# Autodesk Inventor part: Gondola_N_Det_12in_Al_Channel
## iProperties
Shininess: 64.0
Length Units: 11272
Angle Units: 11279
Time Units: 11290
Mass Units: 11286
Length Display Precision: 3
Angle Display Precision: 2
Compacted: True
Part Number: Gondola_N_Det_12in_Al_Channel
Document SubType Name: Modeling
Created: 2004-12
Designer: John Blackburn
Material: Aluminum-6061
Description: AL. Assoc. 8" 6061-T6 Channel
Manufacturer: Standard
Standards Organization: Custom
Density: 0.0
Volumn: 0.0
Area: 0.0
PropertySet Name: Model Information
Control State: 0
Master: False
Checked Out: False
Author: John Blackburn
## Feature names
1. Extrusion1
2. Hole1
3. Hole2
4. Hole3
5. Hole4
6. Hole5
7. Hole6
